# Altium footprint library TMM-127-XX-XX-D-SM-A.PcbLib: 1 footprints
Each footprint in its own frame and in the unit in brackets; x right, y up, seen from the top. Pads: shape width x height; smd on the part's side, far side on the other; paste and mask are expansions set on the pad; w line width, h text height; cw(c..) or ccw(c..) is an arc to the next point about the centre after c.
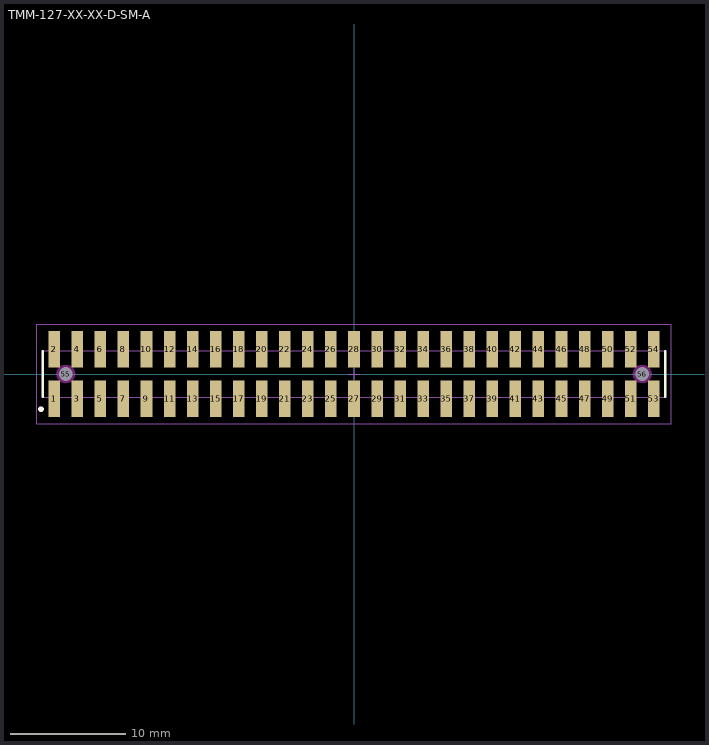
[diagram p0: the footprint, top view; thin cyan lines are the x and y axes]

## TMM-127-XX-XX-D-SM-A [mm] "2.00mm pitch, 54 pin, terminal strip; double row, w/alignment pins, SMT"
height 2.77
pads (56):
  rect 1x3.2 smd mask+0: 1(-26,-2.15) 2(-26,2.15) 3(-24,-2.15) 4(-24,2.15) 5(-22,-2.15) 6(-22,2.15) 7(-20,-2.15) 8(-20,2.15) 9(-18,-2.15) 10(-18,2.15) 11(-16,-2.15) 12(-16,2.15) 13(-14,-2.15) 14(-14,2.15) 15(-12,-2.15) 16(-12,2.15) 17(-10,-2.15) 18(-10,2.15) 19(-8,-2.15) 20(-8,2.15) 21(-6,-2.15) 22(-6,2.15) 23(-4,-2.15) 24(-4,2.15) 25(-2,-2.15) 26(-2,2.15) 27(0,-2.15) 28(0,2.15) 29(2,-2.15) 30(2,2.15) 31(4,-2.15) 32(4,2.15) 33(6,-2.15) 34(6,2.15) 35(8,-2.15) 36(8,2.15) 37(10,-2.15) 38(10,2.15) 39(12,-2.15) 40(12,2.15) 41(14,-2.15) 42(14,2.15) 43(16,-2.15) 44(16,2.15) 45(18,-2.15) 46(18,2.15) 47(20,-2.15) 48(20,2.15) 49(22,-2.15) 50(22,2.15) 51(24,-2.15) 52(24,2.15) 53(26,-2.15) 54(26,2.15)
  round 1 hole 1.2 unplated mask+0: 55(-25,0) 56(25,0)
Top Overlay:
  circle w0.25: c-27.15,-3.05 r0.125
  lines w0.2: -27,-2 -27,2 ; 27,-2 27,2
Keep-Out Layer:
  pour cut-out: 25.807,0 25.779,0.209 25.699,0.403 25.571,0.571 25.403,0.699 25.209,0.779 25,0.807 24.791,0.779 24.597,0.699 24.429,0.571 24.301,0.403 24.221,0.209 24.193,0 24.221,-0.209 24.301,-0.403 24.429,-0.571 24.597,-0.699 24.791,-0.779 25,-0.807 25.209,-0.779 25.403,-0.699 25.571,-0.571 25.699,-0.403 25.779,-0.209
  pour cut-out: -24.193,0 -24.221,0.209 -24.301,0.403 -24.429,0.571 -24.597,0.699 -24.791,0.779 -25,0.807 -25.209,0.779 -25.403,0.699 -25.571,0.571 -25.699,0.403 -25.779,0.209 -25.807,0 -25.779,-0.209 -25.699,-0.403 -25.571,-0.571 -25.403,-0.699 -25.209,-0.779 -25,-0.807 -24.791,-0.779 -24.597,-0.699 -24.429,-0.571 -24.301,-0.403 -24.221,-0.209
Mechanical 12:
  lines w0.001: -27,-2 -27,2 27,2 27,-2 -27,-2
Mechanical 13:
  lines w0.1: -27,-2 -27,2 27,2 27,-2 -27,-2
  text ".Designator" at 0.127,-0.127 h1.52
Mechanical 15:
  lines w0.05: -0.5,0 0.5,0 ; 0,-0.5 0,0.5 ; -27.5,-4.3 -27.5,4.3 27.5,4.3 27.5,-4.3 -27.5,-4.3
